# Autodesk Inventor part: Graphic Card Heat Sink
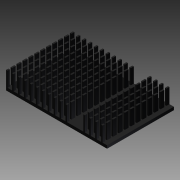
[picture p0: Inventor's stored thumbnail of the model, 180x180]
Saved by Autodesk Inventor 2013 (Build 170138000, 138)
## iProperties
Company: Autodesk Inc.
Created: 2005-12
Part Number: Graphic Card Heat Sink
Document SubType Name: Modeling
Designer: Autodesk Inc.
Density: 1 g/cm^3
Mass: 10.395 g
Surface Area: 187.22 cm^2
Volume: 10.395 cm^3
Material: Allgemein
Title: Personal Computer
Author: Autodesk Inc.
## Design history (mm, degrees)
sketch "Sketch1"
  geometry: L1 (0, 31.5)-(0, -31.5) reference; L2 (-47.6, 0)-(47.6, 0) reference; L3 (-34, 22.5)-(34, 22.5); L4 (34, 22.5)-(34, -22.5); L5 (34, -22.5)-(-34, -22.5); L6 (-34, -22.5)-(-34, 22.5)
  constraints: 8 end point, 2 parallel, 1 horizontal, 1 perpendicular, 2 other
  dimensions: "d0" = 68 distance of L3.start L3.end; "d1" = 45 distance of L5.end L3.start
extrude "Extrusion1" new body sketch "Sketch1" distance "d2" = 12; taper "d3" = 0 deg
sketch "Sketch3"
  geometry: L1 (68, 12)-(0, 12) reference; L2 (0, 0)-(0, 12) reference; L3 (68, 0)-(0, 0) reference; L4 (1, 12)-(4, 12); L5 (4, 12)-(4, 2); L6 (4, 2)-(1, 2); L7 (1, 2)-(1, 12)
  constraints: 8 end point, 2 parallel, 1 horizontal, 1 perpendicular, 1 point on line
  dimensions: "d11" = 2 distance between parallel lines of L3 L6; "d12" = 1 distance between parallel lines of L2 L7; "d13" = 3 distance of L5.end L6.end
extrude "Extrusion3" cut sketch "Sketch3" stored distance "d14" = 12; taper "d15" = 0 deg
sketch "Sketch4"
  geometry: L1 (49, 12)-(41, 12); L2 (41, 12)-(41, 2); L3 (41, 2)-(49, 2); L4 (49, 2)-(49, 12)
  constraints: 8 end point, 2 parallel, 1 horizontal, 1 perpendicular
extrude "Extrusion4" cut sketch "Sketch4" stored distance "d19" = 12; taper "d20" = 0 deg
sketch "Sketch5"
  geometry: L1 (31, -22.5)-(31, 22.5) reference; L2 (-34, -22.5)-(-34, 22.5) reference; L3 (31, 20.5)-(-34, 20.5); L4 (-34, 20.5)-(-34, 19); L5 (-34, 19)-(31, 19); L6 (31, 19)-(31, 20.5); L7 (27, 22.5)-(30, 22.5) reference
  constraints: 8 end point, 2 parallel, 2 point on line, 1 horizontal, 1 perpendicular
  dimensions: "d21" = 2 distance between parallel lines of L3 L7; "d22" = 1.5 distance between parallel lines of L5 L3
extrude "Extrusion5" cut sketch "Sketch5" stored distance "d23" = 12; taper "d24" = 0 deg
pattern_linear "Rectangular Pattern3" dims "d27" = 4
body "Solid1"
pattern_linear "Rectangular Pattern2" dims "d18" = 4
